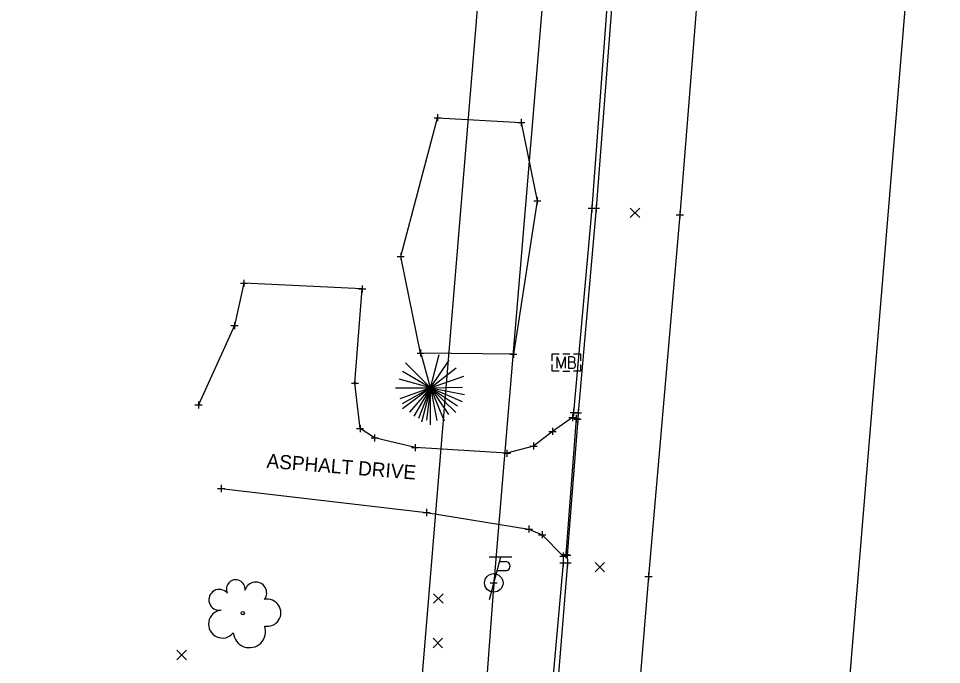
# Model space of a CAD drawing. Extents: x 1380550 to 1381945, y 468927 to 470496.
# Drawn here: x 1381462.2 to 1381592.3, y 469378.6 to 469469.7 of the extents above; entities that cross this region are included whole.
import ezdxf

# ---------------------------------------------------------------- set-up
doc = ezdxf.new("R2010")
doc.units = 0
for name, color, linetype in [('PV_X_COP', 7, 'Continuous'), ('PV_X_Curb', 7, 'Continuous'), ('PV_X_Driveway', 7, 'Continuous'), ('PV_X_EOP', 7, 'Continuous'), ('RD_X_Cells', 7, 'Continuous'), ('RD_X_Text', 7, 'Continuous'), ('RW_X_Esmt_General', 7, 'Continuous'), ('SV_X_Random_Point', 7, 'Continuous'), ('SV_X_Shot_Marker', 7, 'Continuous'), ('UT_X_Electric', 7, 'Continuous'), ('UT_X_Misc_Cells', 7, 'Continuous'), ('UT_X_Telecom', 7, 'Continuous'), ('VG_X_Cells', 7, 'Continuous'), ('VG_X_Shrub_Line_Lt', 7, 'Continuous')]:
    doc.layers.add(name, color=color, linetype=linetype)

msp = doc.modelspace()

# ---------------------------------------------------------------- linework, layer by layer
at = {"layer": 'PV_X_COP'}
msp.add_lwpolyline([(1381585.99, 469815.58), (1381581.29, 469760.78), (1381580.3, 469747.86), (1381578.72, 469729.45), (1381576.78, 469708.95), (1381575.29, 469689.79), (1381572.76, 469657.56), (1381569.36, 469615.7), (1381565.36, 469567.23), (1381561.16, 469537.52), (1381558.94, 469486.81), (1381555.39, 469442.03), (1381550.97, 469391.02), (1381547.28, 469345.9), (1381541.95, 469289.55), (1381537.19, 469231.27), (1381533.05, 469168.09), (1381530.32, 469133.74), (1381523.97, 469065.08), (1381520.12, 469021.37), (1381518.18, 469001.31)], dxfattribs=at)
at = {"layer": 'PV_X_Curb'}
for points in [[(1381546.56, 469490.49), (1381546.46, 469489.61), (1381542.99, 469442.93), (1381540.42, 469414.14), (1381540.26, 469413.42)], [(1381538.96, 469393.9), (1381538.97, 469392.95), (1381537.34, 469375.04), (1381537.07, 469373.85)]]:
    msp.add_lwpolyline(points, dxfattribs=at)
at = {"layer": 'PV_X_Driveway'}
for points in [[(1381540.26, 469413.42), (1381537.45, 469411.48), (1381534.77, 469409.41), (1381531.03, 469408.39), (1381518.07, 469409.2), (1381512.37, 469410.55), (1381510.33, 469411.87), (1381509.61, 469418.3), (1381510.63, 469431.57), (1381493.97, 469432.36), (1381492.63, 469426.39), (1381487.56, 469415.21)], [(1381540.26, 469413.42), (1381540.77, 469413.29), (1381539.31, 469394.1), (1381538.96, 469393.9)], [(1381490.75, 469403.42), (1381519.7, 469400.04), (1381534.11, 469397.71), (1381535.99, 469396.91), (1381538.96, 469393.9)]]:
    msp.add_lwpolyline(points, dxfattribs=at)
at = {"layer": 'PV_X_EOP'}
msp.add_lwpolyline([(1381553.84, 469569.16), (1381551.39, 469538.56), (1381548.86, 469510.86), (1381548.72, 469510.03), (1381547.16, 469490.53), (1381547.16, 469489.45), (1381543.59, 469442.93), (1381541.04, 469414.11), (1381541, 469413.22), (1381539.53, 469394.02), (1381539.58, 469392.93), (1381538.09, 469374.98)], dxfattribs=at)
at = {"layer": 'RD_X_Cells'}
for p, q in [((1381538.88, 469422.4), (1381539.88, 469422.4)), ((1381539.39, 469421.18), (1381539.39, 469421.18)), ((1381538.88, 469419.96), (1381539.88, 469419.96))]:
    msp.add_line(p, q, dxfattribs=at)
for points in [[(1381537.39, 469421.43), (1381537.39, 469422.4), (1381538.36, 469422.4)], [(1381538.09, 469420.38), (1381538.09, 469421.98), (1381538.67, 469420.38), (1381539.22, 469421.98), (1381539.22, 469420.38)], [(1381540.41, 469421.25), (1381540.47, 469421.31), (1381540.51, 469421.35), (1381540.53, 469421.39), (1381540.55, 469421.41), (1381540.57, 469421.46), (1381540.59, 469421.5), (1381540.61, 469421.59), (1381540.61, 469421.63), (1381540.61, 469421.68), (1381540.6, 469421.75), (1381540.57, 469421.82), (1381540.53, 469421.87), (1381540.47, 469421.92), (1381540.42, 469421.94), (1381540.4, 469421.96), (1381540.33, 469421.98), (1381539.72, 469421.98), (1381539.72, 469420.38), (1381540.41, 469420.38), (1381540.5, 469420.43), (1381540.57, 469420.49), (1381540.64, 469420.59), (1381540.67, 469420.71), (1381540.69, 469420.82), (1381540.69, 469420.9), (1381540.66, 469420.97), (1381540.61, 469421.09), (1381540.55, 469421.16), (1381540.41, 469421.25), (1381539.72, 469421.25)], [(1381540.39, 469422.4), (1381541.39, 469422.4), (1381541.39, 469421.43)], [(1381538.36, 469419.96), (1381537.39, 469419.96), (1381537.39, 469420.93)], [(1381541.39, 469420.93), (1381541.39, 469419.96), (1381540.39, 469419.96)]]:
    msp.add_lwpolyline(points, dxfattribs=at)
at = {"layer": 'RW_X_Esmt_General'}
for points in [[(1381490.4, 469029.46), (1381590.2, 470237.18), (1380558.69, 470277.03)], [(1381783.19, 470213.89), (1381648.78, 470217.49), (1381563.79, 469189.03)]]:
    msp.add_lwpolyline(points, dxfattribs=at)
at = {"layer": 'SV_X_Random_Point'}
for p, q in [((1381548.4, 469441.62), (1381549.73, 469442.95)), ((1381548.4, 469442.95), (1381549.73, 469441.62)), ((1381543.45, 469391.67), (1381544.78, 469393.01)), ((1381543.45, 469393.01), (1381544.78, 469391.67)), ((1381520.69, 469387.24), (1381522.03, 469388.58)), ((1381520.69, 469388.58), (1381522.03, 469387.24)), ((1381520.62, 469380.98), (1381521.95, 469382.32)), ((1381520.62, 469382.32), (1381521.95, 469380.98)), ((1381484.53, 469379.29), (1381485.86, 469380.63)), ((1381484.53, 469380.63), (1381485.86, 469379.29))]:
    msp.add_line(p, q, dxfattribs=at)
at = {"layer": 'SV_X_Shot_Marker'}
for p, q in [((1381520.75, 469455.7), (1381521.75, 469455.7)), ((1381521.25, 469456.2), (1381521.25, 469455.2)), ((1381521.25, 469455.7), (1381521.25, 469455.7)), ((1381533.04, 469455.53), (1381533.04, 469454.53)), ((1381532.54, 469455.03), (1381533.54, 469455.03)), ((1381533.04, 469455.03), (1381533.04, 469455.03)), ((1381534.8, 469444.01), (1381535.8, 469444.01)), ((1381535.3, 469444.51), (1381535.3, 469443.51)), ((1381535.3, 469444.01), (1381535.3, 469444.01)), ((1381542.49, 469442.93), (1381543.49, 469442.93)), ((1381542.99, 469443.43), (1381542.99, 469442.43)), ((1381542.99, 469442.93), (1381542.99, 469442.93)), ((1381543.09, 469442.93), (1381544.09, 469442.93)), ((1381543.59, 469443.43), (1381543.59, 469442.43)), ((1381543.59, 469442.93), (1381543.59, 469442.93)), ((1381555.39, 469442.53), (1381555.39, 469441.53)), ((1381554.89, 469442.03), (1381555.89, 469442.03)), ((1381555.39, 469442.03), (1381555.39, 469442.03)), ((1381515.56, 469436.16), (1381516.56, 469436.16)), ((1381516.06, 469436.66), (1381516.06, 469435.66)), ((1381516.06, 469436.16), (1381516.06, 469436.16)), ((1381493.47, 469432.36), (1381494.47, 469432.36)), ((1381493.97, 469432.86), (1381493.97, 469431.86)), ((1381493.97, 469432.36), (1381493.97, 469432.36)), ((1381510.13, 469431.57), (1381511.13, 469431.57)), ((1381510.63, 469432.07), (1381510.63, 469431.07)), ((1381510.63, 469431.57), (1381510.63, 469431.57)), ((1381492.63, 469426.89), (1381492.63, 469425.89)), ((1381492.13, 469426.39), (1381493.13, 469426.39)), ((1381492.63, 469426.39), (1381492.63, 469426.39)), ((1381518.86, 469423.03), (1381518.86, 469422.03)), ((1381518.36, 469422.53), (1381519.36, 469422.53)), ((1381518.86, 469422.53), (1381518.86, 469422.53)), ((1381531.43, 469422.36), (1381532.43, 469422.36)), ((1381531.93, 469422.86), (1381531.93, 469421.86)), ((1381531.93, 469422.36), (1381531.93, 469422.36)), ((1381509.11, 469418.3), (1381510.11, 469418.3)), ((1381509.61, 469418.8), (1381509.61, 469417.8)), ((1381509.61, 469418.3), (1381509.61, 469418.3)), ((1381487.06, 469415.21), (1381488.06, 469415.21)), ((1381487.56, 469415.71), (1381487.56, 469414.71)), ((1381487.56, 469415.21), (1381487.56, 469415.21)), ((1381539.92, 469414.14), (1381540.92, 469414.14)), ((1381540.26, 469413.92), (1381540.26, 469412.92)), ((1381540.26, 469413.92), (1381540.26, 469412.92)), ((1381540.26, 469413.92), (1381540.26, 469412.92)), ((1381540.42, 469414.64), (1381540.42, 469413.64)), ((1381540.42, 469414.14), (1381540.42, 469414.14)), ((1381540.54, 469414.11), (1381541.54, 469414.11)), ((1381541.04, 469414.61), (1381541.04, 469413.61)), ((1381541.04, 469414.11), (1381541.04, 469414.11)), ((1381539.76, 469413.42), (1381540.76, 469413.42)), ((1381539.76, 469413.42), (1381540.76, 469413.42)), ((1381539.76, 469413.42), (1381540.76, 469413.42)), ((1381540.26, 469413.42), (1381540.26, 469413.42)), ((1381540.26, 469413.42), (1381540.26, 469413.42)), ((1381540.26, 469413.42), (1381540.26, 469413.42)), ((1381540.27, 469413.29), (1381541.27, 469413.29)), ((1381540.5, 469413.22), (1381541.5, 469413.22)), ((1381540.77, 469413.79), (1381540.77, 469412.79)), ((1381540.77, 469413.29), (1381540.77, 469413.29)), ((1381541, 469413.72), (1381541, 469412.72)), ((1381541, 469413.22), (1381541, 469413.22)), ((1381509.83, 469411.87), (1381510.83, 469411.87)), ((1381510.33, 469412.37), (1381510.33, 469411.37)), ((1381510.33, 469411.87), (1381510.33, 469411.87)), ((1381536.95, 469411.48), (1381537.95, 469411.48)), ((1381537.45, 469411.98), (1381537.45, 469410.98)), ((1381537.45, 469411.48), (1381537.45, 469411.48)), ((1381511.87, 469410.55), (1381512.87, 469410.55)), ((1381512.37, 469411.05), (1381512.37, 469410.05)), ((1381512.37, 469410.55), (1381512.37, 469410.55)), ((1381517.57, 469409.2), (1381518.57, 469409.2)), ((1381518.07, 469409.7), (1381518.07, 469408.7)), ((1381518.07, 469409.2), (1381518.07, 469409.2)), ((1381531.03, 469408.89), (1381531.03, 469407.89)), ((1381534.27, 469409.41), (1381535.27, 469409.41)), ((1381534.77, 469409.91), (1381534.77, 469408.91)), ((1381534.77, 469409.41), (1381534.77, 469409.41)), ((1381530.53, 469408.39), (1381531.53, 469408.39)), ((1381531.03, 469408.39), (1381531.03, 469408.39)), ((1381490.75, 469403.92), (1381490.75, 469402.92)), ((1381490.25, 469403.42), (1381491.25, 469403.42)), ((1381490.75, 469403.42), (1381490.75, 469403.42)), ((1381519.2, 469400.04), (1381520.2, 469400.04)), ((1381519.7, 469400.54), (1381519.7, 469399.54)), ((1381519.7, 469400.04), (1381519.7, 469400.04)), ((1381533.61, 469397.71), (1381534.61, 469397.71)), ((1381534.11, 469398.21), (1381534.11, 469397.21)), ((1381534.11, 469397.71), (1381534.11, 469397.71)), ((1381535.99, 469397.41), (1381535.99, 469396.41)), ((1381535.49, 469396.91), (1381536.49, 469396.91)), ((1381535.99, 469396.91), (1381535.99, 469396.91)), ((1381538.96, 469394.4), (1381538.96, 469393.4)), ((1381538.96, 469394.4), (1381538.96, 469393.4)), ((1381538.96, 469394.4), (1381538.96, 469393.4)), ((1381539.31, 469394.6), (1381539.31, 469393.6)), ((1381539.53, 469394.52), (1381539.53, 469393.52)), ((1381538.46, 469393.9), (1381539.46, 469393.9)), ((1381538.46, 469393.9), (1381539.46, 469393.9)), ((1381538.46, 469393.9), (1381539.46, 469393.9)), ((1381538.81, 469394.1), (1381539.81, 469394.1)), ((1381538.96, 469393.9), (1381538.96, 469393.9)), ((1381538.96, 469393.9), (1381538.96, 469393.9)), ((1381538.96, 469393.9), (1381538.96, 469393.9)), ((1381538.97, 469393.45), (1381538.97, 469392.45)), ((1381539.03, 469394.02), (1381540.03, 469394.02)), ((1381539.31, 469394.1), (1381539.31, 469394.1)), ((1381539.53, 469394.02), (1381539.53, 469394.02)), ((1381539.58, 469393.43), (1381539.58, 469392.43)), ((1381538.47, 469392.95), (1381539.47, 469392.95)), ((1381538.97, 469392.95), (1381538.97, 469392.95)), ((1381539.08, 469392.93), (1381540.08, 469392.93)), ((1381539.58, 469392.93), (1381539.58, 469392.93)), ((1381529.17, 469390.62), (1381529.17, 469389.62)), ((1381529.17, 469390.62), (1381529.17, 469389.62)), ((1381550.47, 469391.02), (1381551.47, 469391.02)), ((1381550.97, 469391.52), (1381550.97, 469390.52)), ((1381550.97, 469391.02), (1381550.97, 469391.02)), ((1381528.67, 469390.12), (1381529.67, 469390.12)), ((1381528.67, 469390.12), (1381529.67, 469390.12)), ((1381529.17, 469390.12), (1381529.17, 469390.12)), ((1381529.17, 469390.12), (1381529.17, 469390.12))]:
    msp.add_line(p, q, dxfattribs=at)
at = {"layer": 'UT_X_Electric'}
msp.add_lwpolyline([(1381665.56, 470247.4), (1381595.79, 470220.83), (1381581.26, 470018.2), (1381571.97, 469887.64), (1381559.77, 469757.41), (1381543.86, 469565.78), (1381529.17, 469390.12), (1381515.28, 469203.1), (1381540.8, 469054.26)], dxfattribs=at)
at = {"layer": 'UT_X_Misc_Cells'}
for p, q in [((1381530.13, 469393.72), (1381528.52, 469387.72)), ((1381531.73, 469393.72), (1381528.53, 469393.72)), ((1381529.97, 469393.12), (1381530.82, 469393.12)), ((1381529.63, 469391.85), (1381530.82, 469391.85))]:
    msp.add_line(p, q, dxfattribs=at)
msp.add_circle((1381529.17, 469390.12), 1.3, dxfattribs=at)
msp.add_arc((1381530.83, 469392.48), 0.638, 268.8767, 91.1233, dxfattribs=at)
at = {"layer": 'UT_X_Telecom'}
msp.add_lwpolyline([(1381665.56, 470247.4), (1381595.35, 470217.51), (1381581.26, 470018.2), (1381571.97, 469887.64), (1381559.77, 469757.41), (1381543.86, 469565.78), (1381529.17, 469390.12), (1381515.28, 469203.1), (1381540.8, 469054.26)], dxfattribs=at)
at = {"layer": 'VG_X_Cells'}
for p, q in [((1381520.24, 469417.64), (1381519, 469422.25)), ((1381520.24, 469417.64), (1381521.49, 469422.34)), ((1381520.24, 469417.64), (1381516.75, 469421.13)), ((1381520.24, 469417.64), (1381522.89, 469421.52)), ((1381520.24, 469417.64), (1381523.89, 469420.44)), ((1381520.24, 469417.64), (1381516.33, 469419.94)), ((1381520.24, 469417.64), (1381524.97, 469419.25)), ((1381520.24, 469417.64), (1381515.82, 469418.82)), ((1381515.3, 469417.64), (1381520.24, 469417.64)), ((1381520.24, 469417.64), (1381515.95, 469416.08)), ((1381520.24, 469417.64), (1381516.25, 469415.36)), ((1381520.24, 469417.64), (1381516.33, 469414.64)), ((1381520.24, 469417.64), (1381517.29, 469414.17)), ((1381520.24, 469417.64), (1381517.92, 469413.62)), ((1381520.24, 469417.64), (1381518.57, 469413.3)), ((1381520.24, 469417.64), (1381518.97, 469412.78)), ((1381520.24, 469417.64), (1381519.69, 469413.05)), ((1381520.24, 469417.64), (1381524.75, 469417.73)), ((1381520.24, 469412.4), (1381520.24, 469417.64)), ((1381520.24, 469417.64), (1381521.16, 469413)), ((1381520.24, 469417.64), (1381522.17, 469412.97)), ((1381520.24, 469417.64), (1381522.77, 469413.85)), ((1381520.24, 469417.64), (1381523.82, 469414.12)), ((1381520.24, 469417.64), (1381524.06, 469415.08)), ((1381520.24, 469417.64), (1381524.7, 469415.7)), ((1381520.24, 469417.64), (1381525.06, 469416.68))]:
    msp.add_line(p, q, dxfattribs=at)
msp.add_circle((1381493.8, 469385.86), 0.24, dxfattribs=at)
for centre, radius, start, end in [((1381492.81, 469389.23), 1.32, 354.0047, 205.9741), ((1381490.49, 469387.73), 1.47, 39.0625, 279.5412), ((1381495.62, 469388.69), 1.55, 323.83, 165.0376), ((1381497.26, 469385.9), 1.91, 259.1453, 101.4596), ((1381490.94, 469384.31), 1.97, 96.1722, 320.5737), ((1381494.74, 469383.26), 2.28, 184.9476, 19.4572)]:
    msp.add_arc(centre, radius, start, end, dxfattribs=at)
at = {"layer": 'VG_X_Shrub_Line_Lt'}
msp.add_lwpolyline([(1381533.04, 469455.03), (1381535.3, 469444.01), (1381531.93, 469422.36), (1381518.86, 469422.53), (1381516.06, 469436.16), (1381521.25, 469455.7)], close=True, dxfattribs=at)

# ---------------------------------------------------------------- texts
at = {"layer": 'RD_X_Text'}
msp.add_text('ASPHALT DRIVE', height=2, rotation=355.4428, dxfattribs=at).set_placement((1381497.1, 469406.35))

doc.saveas('drawing.dxf')
